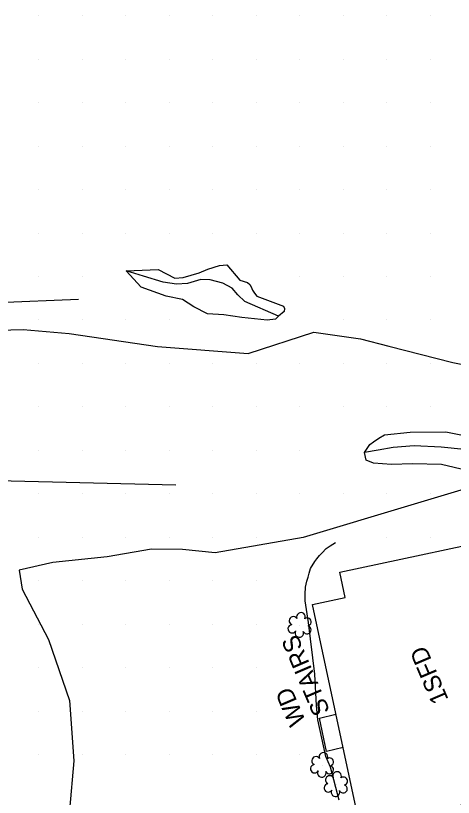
# Model space of a CAD drawing. Extents: x 1548934 to 1561348, y 809680 to 824075.
# Drawn here: x 1552024.7 to 1552125.4, y 810460.2 to 810640 of the extents above; entities that cross this region are included whole.
import ezdxf

# ---------------------------------------------------------------- set-up
doc = ezdxf.new("R2010")
doc.units = 0
for name, color, linetype in [('E_NCDOT_Vertical_Profile_Ground_Line', 7, 'Continuous'), ('Exist Building', 7, 'Continuous'), ('Exist Building Foundations Text', 7, 'Continuous'), ('Exist DTM QL2 LIDAR Elevation Point', 7, 'Continuous'), ('Exist Other Culture Area Outline', 7, 'Continuous'), ('Exist Other Culture Area Outline Text', 7, 'Continuous'), ('Exist Vegetation Shrub CELL', 7, 'Continuous'), ('Exist Vegetation Woods Line', 7, 'Continuous'), ('P_NCDOT_Vertical_Profile_Grade_Minor_Road', 7, 'Continuous'), ('P_RDY_Dimension_Text', 7, 'Continuous'), ('PH Exist DTM Breakline', 7, 'Continuous')]:
    doc.layers.add(name, color=color, linetype=linetype)

msp = doc.modelspace()

# ---------------------------------------------------------------- linework, layer by layer
at = {"layer": 'E_NCDOT_Vertical_Profile_Ground_Line'}
for points in [[(1552269.12, 810011.85), (1552259.92, 810023.16), (1552240.77, 810045.39), (1552214.34, 810080.42), (1552187.87, 810115.32), (1552162.13, 810150.99), (1552135.64, 810187.58), (1552109.72, 810225.45), (1552084.15, 810264.06), (1552058.91, 810303.06), (1552035.06, 810342.6), (1552011.64, 810381.93), (1551989.04, 810421.64), (1551966.75, 810462.54), (1551944.7, 810504.81), (1551922.38, 810547.42), (1551904.22, 810585.98), (1551891.94, 810609.51), (1551888.01, 810619.12)], [(1552253.41, 809998.89), (1552244.07, 810010.35), (1552226, 810034.01), (1552199.08, 810069.05), (1552172.73, 810104.35), (1552146.5, 810139.67), (1552120.17, 810176.34), (1552094.24, 810214.53), (1552068.08, 810253.47), (1552042.84, 810293.18), (1552018.16, 810332.72), (1551995.31, 810372.57), (1551972.35, 810412.52), (1551950.07, 810453.78), (1551927.46, 810496.24), (1551905.62, 810539.48), (1551886.94, 810576.33), (1551876.35, 810599.17), (1551872.14, 810607.03)]]:
    msp.add_open_spline(points, degree=3, dxfattribs=at)
at = {"layer": 'Exist Building'}
msp.add_lwpolyline([(1552099.25, 810511.94), (1552142.43, 810521.19), (1552149.46, 810488.38), (1552136.3, 810485.57), (1552141.47, 810461.43), (1552137.51, 810460.58), (1552137.74, 810459.53), (1552129.3, 810457.72), (1552129.07, 810458.77), (1552124.09, 810457.7), (1552124.32, 810456.65), (1552115.66, 810454.8), (1552115.42, 810455.89), (1552111.82, 810455.12), (1552111.61, 810456.08), (1552103.73, 810454.4), (1552092.99, 810504.54), (1552100.49, 810506.15)], close=True, dxfattribs=at)
at = {"layer": 'Exist DTM QL2 LIDAR Elevation Point'}
for p, q in [((1552030.02, 810639.98), (1552030.02, 810639.98)), ((1552040.02, 810639.98), (1552040.02, 810639.98)), ((1552050.02, 810639.98), (1552050.02, 810639.98)), ((1552060.02, 810639.98), (1552060.02, 810639.98)), ((1552070.02, 810639.98), (1552070.02, 810639.98)), ((1552080.03, 810639.98), (1552080.03, 810639.98)), ((1552090.03, 810639.98), (1552090.03, 810639.98)), ((1552100.03, 810639.98), (1552100.03, 810639.98)), ((1552110.03, 810639.98), (1552110.03, 810639.98)), ((1552120.03, 810639.98), (1552120.03, 810639.98)), ((1552030.02, 810629.98), (1552030.02, 810629.98)), ((1552040.02, 810629.98), (1552040.02, 810629.98)), ((1552050.02, 810629.98), (1552050.02, 810629.98)), ((1552060.02, 810629.98), (1552060.02, 810629.98)), ((1552070.02, 810629.98), (1552070.02, 810629.98)), ((1552080.03, 810629.98), (1552080.03, 810629.98)), ((1552090.03, 810629.98), (1552090.03, 810629.98)), ((1552100.03, 810629.98), (1552100.03, 810629.98)), ((1552110.03, 810629.98), (1552110.03, 810629.98)), ((1552120.03, 810629.98), (1552120.03, 810629.98)), ((1552030.02, 810619.98), (1552030.02, 810619.98)), ((1552040.02, 810619.98), (1552040.02, 810619.98)), ((1552050.02, 810619.98), (1552050.02, 810619.98)), ((1552060.02, 810619.98), (1552060.02, 810619.98)), ((1552070.02, 810619.98), (1552070.02, 810619.98)), ((1552080.03, 810619.98), (1552080.03, 810619.98)), ((1552090.03, 810619.98), (1552090.03, 810619.98)), ((1552100.03, 810619.98), (1552100.03, 810619.98)), ((1552110.03, 810619.98), (1552110.03, 810619.98)), ((1552120.03, 810619.98), (1552120.03, 810619.98)), ((1552030.02, 810609.98), (1552030.02, 810609.98)), ((1552040.02, 810609.98), (1552040.02, 810609.98)), ((1552050.02, 810609.98), (1552050.02, 810609.98)), ((1552060.02, 810609.98), (1552060.02, 810609.98)), ((1552070.02, 810609.98), (1552070.02, 810609.98)), ((1552080.03, 810609.98), (1552080.03, 810609.98)), ((1552090.03, 810609.98), (1552090.03, 810609.98)), ((1552100.03, 810609.98), (1552100.03, 810609.98)), ((1552110.03, 810609.98), (1552110.03, 810609.98)), ((1552120.03, 810609.98), (1552120.03, 810609.98)), ((1552030.02, 810599.98), (1552030.02, 810599.98)), ((1552040.02, 810599.98), (1552040.02, 810599.98)), ((1552050.02, 810599.98), (1552050.02, 810599.98)), ((1552060.02, 810599.98), (1552060.02, 810599.98)), ((1552070.02, 810599.98), (1552070.02, 810599.98)), ((1552080.03, 810599.98), (1552080.03, 810599.98)), ((1552090.03, 810599.98), (1552090.03, 810599.98)), ((1552100.03, 810599.98), (1552100.03, 810599.98)), ((1552110.03, 810599.98), (1552110.03, 810599.98)), ((1552120.03, 810599.98), (1552120.03, 810599.98)), ((1552030.02, 810589.98), (1552030.02, 810589.98)), ((1552040.02, 810589.98), (1552040.02, 810589.98)), ((1552050.02, 810589.98), (1552050.02, 810589.98)), ((1552060.02, 810589.98), (1552060.02, 810589.98)), ((1552070.02, 810589.98), (1552070.02, 810589.98)), ((1552080.03, 810589.98), (1552080.03, 810589.98)), ((1552090.03, 810589.98), (1552090.03, 810589.98)), ((1552100.03, 810589.98), (1552100.03, 810589.98)), ((1552110.03, 810589.98), (1552110.03, 810589.98)), ((1552120.03, 810589.98), (1552120.03, 810589.98)), ((1552030.02, 810579.98), (1552030.02, 810579.98)), ((1552040.02, 810579.98), (1552040.02, 810579.98)), ((1552090.03, 810579.98), (1552090.03, 810579.98)), ((1552100.03, 810579.98), (1552100.03, 810579.98)), ((1552110.03, 810579.98), (1552110.03, 810579.98)), ((1552120.03, 810579.98), (1552120.03, 810579.98)), ((1552030.02, 810569.98), (1552030.02, 810569.98)), ((1552040.02, 810569.98), (1552040.02, 810569.98)), ((1552050.02, 810569.98), (1552050.02, 810569.98)), ((1552060.02, 810569.98), (1552060.02, 810569.98)), ((1552100.03, 810569.98), (1552100.03, 810569.98)), ((1552110.03, 810569.98), (1552110.03, 810569.98)), ((1552120.03, 810569.98), (1552120.03, 810569.98)), ((1552030.02, 810559.98), (1552030.02, 810559.98)), ((1552040.02, 810559.98), (1552040.02, 810559.98)), ((1552050.02, 810559.98), (1552050.02, 810559.98)), ((1552060.02, 810559.98), (1552060.02, 810559.98)), ((1552070.02, 810559.98), (1552070.02, 810559.98)), ((1552080.03, 810559.98), (1552080.03, 810559.98)), ((1552090.03, 810559.98), (1552090.03, 810559.98)), ((1552100.03, 810559.98), (1552100.03, 810559.98)), ((1552110.03, 810559.98), (1552110.03, 810559.98)), ((1552120.03, 810559.98), (1552120.03, 810559.98)), ((1552030.02, 810549.97), (1552030.02, 810549.97)), ((1552040.02, 810549.97), (1552040.02, 810549.97)), ((1552050.02, 810549.97), (1552050.02, 810549.97)), ((1552060.02, 810549.97), (1552060.02, 810549.97)), ((1552070.02, 810549.97), (1552070.02, 810549.97)), ((1552080.03, 810549.97), (1552080.03, 810549.97)), ((1552090.03, 810549.97), (1552090.03, 810549.97)), ((1552100.03, 810549.97), (1552100.03, 810549.97)), ((1552110.03, 810549.97), (1552110.03, 810549.97)), ((1552120.03, 810549.97), (1552120.03, 810549.97)), ((1552030.02, 810539.97), (1552030.02, 810539.97)), ((1552040.02, 810539.97), (1552040.02, 810539.97)), ((1552050.02, 810539.97), (1552050.02, 810539.97)), ((1552060.02, 810539.97), (1552060.02, 810539.97)), ((1552070.02, 810539.97), (1552070.02, 810539.97)), ((1552080.03, 810539.97), (1552080.03, 810539.97)), ((1552090.03, 810539.97), (1552090.03, 810539.97)), ((1552030.02, 810529.97), (1552030.02, 810529.97)), ((1552040.02, 810529.97), (1552040.02, 810529.97)), ((1552050.02, 810529.97), (1552050.02, 810529.97)), ((1552060.02, 810529.97), (1552060.02, 810529.97)), ((1552070.02, 810529.97), (1552070.02, 810529.97)), ((1552080.03, 810529.97), (1552080.03, 810529.97)), ((1552090.03, 810529.97), (1552090.03, 810529.97)), ((1552100.03, 810529.97), (1552100.03, 810529.97)), ((1552110.03, 810529.97), (1552110.03, 810529.97)), ((1552120.03, 810529.97), (1552120.03, 810529.97)), ((1552030.02, 810519.97), (1552030.02, 810519.97)), ((1552040.02, 810519.97), (1552040.02, 810519.97)), ((1552050.02, 810519.97), (1552050.02, 810519.97)), ((1552060.02, 810519.97), (1552060.02, 810519.97)), ((1552070.02, 810519.97), (1552070.02, 810519.97)), ((1552080.03, 810519.97), (1552080.03, 810519.97)), ((1552090.03, 810519.97), (1552090.03, 810519.97)), ((1552110.03, 810519.97), (1552110.03, 810519.97)), ((1552120.03, 810519.97), (1552120.03, 810519.97)), ((1552030.02, 810509.97), (1552030.02, 810509.97)), ((1552040.02, 810509.97), (1552040.02, 810509.97)), ((1552050.02, 810509.97), (1552050.02, 810509.97)), ((1552060.02, 810509.97), (1552060.02, 810509.97)), ((1552070.02, 810509.97), (1552070.02, 810509.97)), ((1552080.03, 810509.97), (1552080.03, 810509.97)), ((1552030.02, 810499.97), (1552030.02, 810499.97)), ((1552040.02, 810499.97), (1552040.02, 810499.97)), ((1552050.02, 810499.97), (1552050.02, 810499.97)), ((1552060.02, 810499.97), (1552060.02, 810499.97)), ((1552070.02, 810499.97), (1552070.02, 810499.97)), ((1552080.03, 810499.97), (1552080.03, 810499.97)), ((1552030.02, 810489.97), (1552030.02, 810489.97)), ((1552040.02, 810489.97), (1552040.02, 810489.97)), ((1552050.02, 810489.97), (1552050.02, 810489.97)), ((1552060.02, 810489.97), (1552060.02, 810489.97)), ((1552070.02, 810489.97), (1552070.02, 810489.97)), ((1552080.03, 810489.97), (1552080.03, 810489.97)), ((1552030.02, 810479.97), (1552030.02, 810479.97)), ((1552040.02, 810479.97), (1552040.02, 810479.97)), ((1552050.02, 810479.97), (1552050.02, 810479.97)), ((1552060.02, 810479.97), (1552060.02, 810479.97)), ((1552070.02, 810479.97), (1552070.02, 810479.97)), ((1552080.03, 810479.97), (1552080.03, 810479.97)), ((1552030.02, 810469.97), (1552030.02, 810469.97)), ((1552040.02, 810469.97), (1552040.02, 810469.97)), ((1552050.02, 810469.97), (1552050.02, 810469.97)), ((1552060.02, 810469.97), (1552060.02, 810469.97)), ((1552070.02, 810469.97), (1552070.02, 810469.97)), ((1552080.03, 810469.97), (1552080.03, 810469.97)), ((1552090.03, 810469.97), (1552090.03, 810469.97))]:
    msp.add_line(p, q, dxfattribs=at)
at = {"layer": 'Exist Other Culture Area Outline'}
msp.add_lwpolyline([(1552100.03, 810471.64), (1552096.19, 810470.76), (1552094.63, 810478.39), (1552098.39, 810479.32)], dxfattribs=at)
at = {"layer": 'Exist Vegetation Shrub CELL'}
for p, q in [((1552090.1, 810499.65), (1552090.1, 810499.65)), ((1552095.27, 810467.45), (1552095.27, 810467.45)), ((1552098.42, 810463.05), (1552098.42, 810463.05))]:
    msp.add_line(p, q, dxfattribs=at)
for centre, radius, start, end in [((1552090.33, 810501.69), 0.99, 334.8391, 200.4717), ((1552088.61, 810500.78), 0.968, 35.8908, 245.4216), ((1552091.77, 810500.52), 0.929, 284.4567, 126.0861), ((1552088.3, 810498.94), 0.955, 95.1099, 327.9534), ((1552091.73, 810498.72), 0.937, 204.9913, 73.4601), ((1552089.97, 810497.97), 0.984, 151.2797, 21.387), ((1552095.5, 810469.49), 0.99, 334.8391, 200.4717), ((1552093.79, 810468.58), 0.968, 35.8908, 245.4216), ((1552096.94, 810468.32), 0.929, 284.4567, 126.0861), ((1552093.47, 810466.75), 0.955, 95.1099, 327.9534), ((1552096.91, 810466.52), 0.937, 204.9913, 73.4601), ((1552095.14, 810465.77), 0.984, 151.2797, 21.387), ((1552096.94, 810464.18), 0.968, 35.8908, 245.4216), ((1552098.65, 810465.09), 0.99, 334.8391, 200.4717), ((1552096.62, 810462.34), 0.955, 95.1099, 327.9534), ((1552100.09, 810463.92), 0.929, 284.4567, 126.0861), ((1552098.29, 810461.36), 0.984, 151.2797, 21.387), ((1552100.06, 810462.12), 0.937, 204.9913, 73.4601)]:
    msp.add_arc(centre, radius, start, end, dxfattribs=at)
at = {"layer": 'Exist Vegetation Woods Line'}
for points in [[(1552015.11, 810567.52), (1552026.47, 810567.76), (1552037.03, 810566.84), (1552057.34, 810563.86), (1552078.2, 810562.28), (1552093.28, 810567.15), (1552104.06, 810565.62), (1552110.56, 810563.94), (1552125.26, 810560.17), (1552138.9, 810557.41)], [(1552139.59, 810534.59), (1552090.86, 810519.98), (1552070.63, 810516.4), (1552063.07, 810517.17), (1552055.94, 810517.23), (1552045.8, 810515.52), (1552033.27, 810514.17), (1552025.56, 810512.46), (1552026.27, 810508.03), (1552032.3, 810496.48), (1552037.14, 810482.42), (1552038.11, 810468.55), (1552037.1, 810457.26)]]:
    msp.add_lwpolyline(points, dxfattribs=at)
at = {"layer": 'P_NCDOT_Vertical_Profile_Grade_Minor_Road'}
msp.add_open_spline([(1551879.82, 810614.21), (1551884.04, 810605.38), (1551895.16, 810581.81), (1551913.82, 810543.91), (1551935.87, 810500.72), (1551958.31, 810458.4), (1551980.95, 810417.47), (1552003.45, 810377.53), (1552026.54, 810337.94), (1552050.88, 810298.39), (1552075.93, 810258.79), (1552101.83, 810219.9), (1552127.9, 810181.92), (1552154.01, 810145.19), (1552180.07, 810109.84), (1552206.52, 810074.71), (1552233.37, 810039.85), (1552251.61, 810016.53), (1552260.84, 810005.28)], degree=3, dxfattribs=at)
at = {"layer": 'P_RDY_Dimension_Text'}
for p, q in [((1551976.13, 810572.1), (1552039.2, 810574.75)), ((1551975.71, 810534.13), (1552061.55, 810532.04))]:
    msp.add_line(p, q, dxfattribs=at)
at = {"layer": 'PH Exist DTM Breakline'}
for points in [[(1552085.21, 810570.85), (1552077.46, 810574.24), (1552075.8, 810575.79), (1552074.55, 810577.28), (1552072.38, 810578.46), (1552069.43, 810579.2), (1552067.32, 810579.29), (1552064.29, 810578.34), (1552061.69, 810578.18), (1552058.68, 810578.66), (1552054.13, 810580.02), (1552050.14, 810581.28), (1552057.49, 810581.57), (1552061.31, 810579.57), (1552063.26, 810579.74), (1552066.94, 810580.86), (1552068.9, 810581.69), (1552071.63, 810582.53), (1552073.32, 810582.69), (1552076.27, 810579.14), (1552078.08, 810578.62), (1552078.57, 810578.14), (1552078.89, 810577.61), (1552079.23, 810576.83), (1552079.67, 810576.14), (1552080.19, 810575.42), (1552086.32, 810573.13), (1552086.56, 810572.64), (1552086.48, 810571.96), (1552085.21, 810570.85), (1552084.47, 810570.2), (1552082.59, 810569.92), (1552076.73, 810570.55), (1552072.63, 810571.16), (1552068.88, 810571.37), (1552065.7, 810573.02), (1552063.1, 810574.68), (1552059.37, 810575.49), (1552053.6, 810577.51), (1552050.14, 810581.28)], [(1552135.06, 810538.88), (1552127.83, 810540.15), (1552122.56, 810540.74), (1552116.4, 810541.01), (1552111.55, 810540.67), (1552108.08, 810540.06), (1552104.92, 810539.51), (1552106.2, 810541.32), (1552107.04, 810541.98), (1552108.27, 810542.82), (1552109.54, 810543.54), (1552115.44, 810544.21), (1552123.68, 810544.24), (1552130.92, 810542.83), (1552138.05, 810542.05)], [(1552135.57, 810533.68), (1552122.63, 810536.77), (1552116, 810536.87), (1552111.15, 810536.76), (1552107.01, 810537.03), (1552105.37, 810537.75), (1552104.92, 810539.51)], [(1552099.15, 810459.5), (1552097.16, 810467.09), (1552096.04, 810469.6), (1552094.22, 810477.97), (1552093.94, 810481.28), (1552093.56, 810488.5), (1552092.09, 810500.4), (1552091.29, 810505.41), (1552091.34, 810506.91), (1552091.4, 810508.5), (1552091.71, 810509.91), (1552091.97, 810510.81), (1552092.22, 810511.75), (1552092.56, 810512.81), (1552093.55, 810514.42), (1552093.99, 810515.07), (1552094.62, 810515.83), (1552095.22, 810516.41), (1552096.17, 810517.38), (1552097.07, 810518.01), (1552098.31, 810518.81)]]:
    msp.add_lwpolyline(points, dxfattribs=at)

# ---------------------------------------------------------------- texts
at = {"layer": 'Exist Building Foundations Text'}
msp.add_text('1SFD', height=4.02, rotation=113.1116, dxfattribs=at).set_placement((1552124.33, 810482.7))
at = {"layer": 'Exist Other Culture Area Outline Text'}
for s, p in [('STAIRS', (1552097.08, 810480.02)), ('WD', (1552091.53, 810477.64))]:
    msp.add_text(s, height=4.02, rotation=113.1736, dxfattribs=at).set_placement(p)

doc.saveas('drawing.dxf')
